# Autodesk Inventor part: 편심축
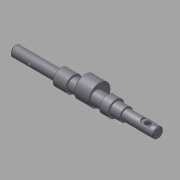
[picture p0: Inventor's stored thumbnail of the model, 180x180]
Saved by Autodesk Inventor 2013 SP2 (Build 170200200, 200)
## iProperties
Company: 한국ATC센터
Created: 2015-12
Part Number: 편심축
Document SubType Name: Modeling
Designer: mdu
Density: 7.86 g/cm^3
Mass: 248.518 g
Surface Area: 94.9962 cm^2
Volume: 31.6181 cm^3
Material: 강철, 연강
Author: mdu
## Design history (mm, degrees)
sketch "스케치1"
  geometry: L1 (-84.5, 0)-(84.5, 0); L2 (-84.5, 0)-(-84.5, 6); L3 (-84.5, 6)-(-30.5, 6); L4 (-30.5, 6)-(-30.5, 9.5); L5 (-30.5, 9.5)-(-15.5, 9.5); L6 (-15.5, 9.5)-(-15.5, 7.5); L7 (-15.5, 7.5)-(46.5, 7.5); L8 (84.5, 6)-(84.5, 0); L9 (34.5, 7.5)-(34.5, 9.5); L10 (34.5, 9.5)-(24.5, 9.5); L11 (24.5, 9.5)-(24.5, 7.5); L12 (46.5, 7.5)-(46.5, 6); L13 (46.5, 6)-(84.5, 6); 2 further points
  constraints: 26 end point, 6 parallel, 6 perpendicular, 2 point on line, 1 coincident, 1 horizontal, 1 midpoint
  dimensions: "d1" = 12 diameter of L3 L1; "d2" = 15 diameter of L7 L1; "d4" = 15 distance of L4.end L5.end; "d5" = 19 diameter of L5 L1; "d24" = 10 distance of L9.end L10.end; "d25" = 19 diameter of L10 L1; "d27" = 40 distance between parallel lines of L11 L6; "d28" = 54 distance of L2.end L3.end; "d29" = 50 distance between parallel lines of L8 L9; "d41" = 38 distance between parallel lines of L8 L12; "d42" = 12 diameter of L13 L1
revolve "회전1" stored, may be unused: angle "d6" = 90 deg
node "작업 평면1"
sketch "스케치2"
  geometry: C1 r 7.5 at (0, 0) reference; C2 r 12.5 at (0, 4.5); 1 further point
  constraints: 1 centre point, 1 vertical alignment
  dimensions: "d8" = 4.5 distance of point (0, 0) C2.centre; "d9" = 25 diameter of C2
extrude "돌출1" join sketch "스케치2" distance "d10" = 18; taper "d11" = 0 deg
chamfer "모따기1" distance "d12" = 1; stored, may be unused: second distance "d13" = 2, angle "d14" = 45 deg
chamfer "모따기2" distance "d15" = 0.5; stored, may be unused: second distance "d16" = 2, angle "d17" = 45 deg
node "작업 평면2"
sketch "스케치3"
  geometry: L1 (4, -2)-(18, -2); L2 (18, 2)-(4, 2); L3 (27, 5)-(27, -5) reference; A1 r 2 centre (18, 0) between (18, -2) and (18, 2); A2 r 2 centre (4, 0) between (4, 2) and (4, -2); 2 further points
  constraints: 4 end point, 4 point on circle, 4 tangent, 2 centre point, 1 horizontal, 1 horizontal alignment, 1 midpoint, 1 parallel
  dimensions: "d18" = 7 distance edge to line of A1 L3; "d19" = 4 distance between parallel lines of L2 L1; "d20" = 18 dimension on A1 A2
extrude "돌출2" cut sketch "스케치3" distance "d21" = 2.5; taper "d22" = 0 deg
revolve "회전2" stored, may be unused: angle "d26" = 90 deg
node "작업 평면3"
sketch "스케치4"
  geometry: L1 (44, 5)-(44, -5) reference; 2 further points
  constraints: 1 horizontal alignment
  dimensions: "d30" = 12 distance from line of point (32, 0) L1
hole "구멍1" sketch "스케치4" at (32, 0) diameter "d31" = 6; stored, may be unused: countersink angle "d35" = 90 deg, drill point angle "d37" = 118 deg; dims "d32" = 6, "d33" = 14, "d34" = 3, "d36" = 8
node "작업 평면4"
sketch "스케치5"
  geometry: C1 r 3 at (32, 0) reference; C2 r 8 at (32, 0); 2 further points
  constraints: 1 centre point, 1 coincident, 1 other
  dimensions: "d38" = 16 diameter of C2
extrude "돌출3" cut sketch "스케치5" distance "d39" = 3; taper "d40" = 0 deg
sketch "스케치6"
  geometry: L1 (-83.5, -6)-(-30.5, -6) reference; L2 (-84.5, -5)-(-84.5, 5) reference; L3 (-83.5, 6)-(-30.5, 6) reference; L4 (-62.5, 6)-(-62.5, -6); L5 (-62.5, -6)-(-61, -6); L6 (-62.5, -4.5)-(-61, -6); L7 (-62.5, -6)-(-62.5, -4.5); 2 further points
  constraints: 8 end point, 4 point on line, 2 perpendicular, 1 coincident
  dimensions: "d43" = 22 distance between parallel lines of L4 L2; "d44" = 45 deg angle of L6 L7; "d45" = 3 diameter of L5.end L4
revolve "회전3" stored, may be unused: angle "d46" = 90 deg
node "작업점1"
chamfer "모따기3" distance "d47" = 0.5; stored, may be unused: second distance "d48" = 2, angle "d49" = 45 deg
node "솔리드1"
node "투영된 루프1"
other parameters: "d7" = 8.5
